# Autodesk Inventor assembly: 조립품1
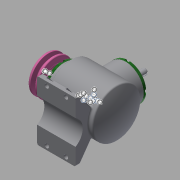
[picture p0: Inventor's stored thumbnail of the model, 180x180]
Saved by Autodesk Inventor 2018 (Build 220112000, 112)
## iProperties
Created: 2021-04
Part Number: 조립품1
Material: 일반
Document SubType Name: Assembly
Designer: home
Author: home
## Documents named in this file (16)
- C:\Users\home\Desktop\710407V1016\조립품1.iam
- C:\Users\home\Desktop\710407V1016\본체.ipt
- C:\Users\home\Desktop\710407V1016\커버.ipt
- C:\Users\home\Desktop\710407V1016\베어링 6203.ipt
- C:\Users\home\Desktop\710407V1016\오일실 17 x 32 x 8.ipt
- C:\Users\home\Desktop\710407V1016\메인 축.ipt
- 메인 축.ipt
- C:\Users\home\Desktop\710407V1016\서브 축.ipt
- 서브 축.ipt
- C:\Users\home\Desktop\710407V1016\키 5 x 5 x 14.ipt
- C:\Users\home\Desktop\710407V1016\키 4 x 4 x 14.ipt
- C:\Users\home\Desktop\710407V1016\메인 베벨기어.ipt
- C:\Users\home\Desktop\710407V1016\서브 베벨기어.ipt
- C:\Users\home\Desktop\710407V1016\V-벨트풀리.ipt
- C:\Users\home\Desktop\710407V1016\육각볼트 M4 x 8.ipt
- C:\Users\home\Desktop\710407V1016\와셔 4 x 16.ipt
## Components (1 placed, 1 different names)
1. V-벨트풀리:1 — 각도:6
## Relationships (1: Angle 1)
- 각도:6 [Angle]: V-벨트풀리:1
